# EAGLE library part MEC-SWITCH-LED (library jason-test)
MEC switch with LED
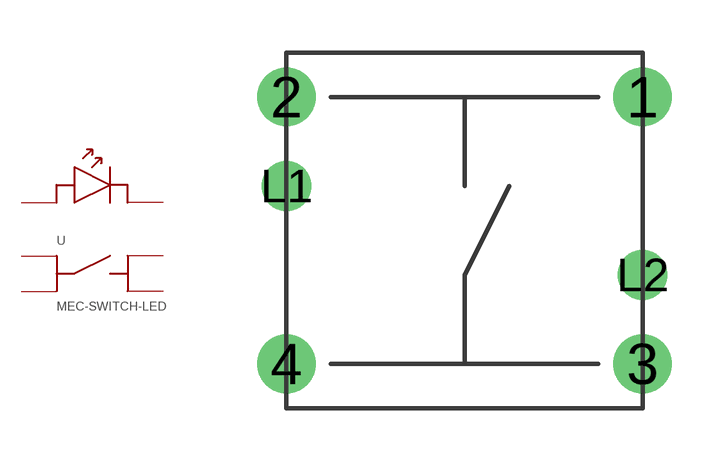
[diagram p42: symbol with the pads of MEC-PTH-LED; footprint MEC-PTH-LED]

Designator prefix -

## MEC-SWITCH-LED  [MEC-PTH-LED]
1  A1
2  A2
3  B1
4  B2
L1  L1
L2  L2

## Footprint MEC-PTH-LED (pad centres in mm)
drill 1 pad 1.676 round: 1 5.08,3.81; 2 -5.08,3.81; 3 5.08,-3.81; 4 -5.08,-3.81
drill 0.8 pad 1.422 round: L1 -5.08,1.27; L2 5.08,-1.27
